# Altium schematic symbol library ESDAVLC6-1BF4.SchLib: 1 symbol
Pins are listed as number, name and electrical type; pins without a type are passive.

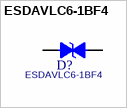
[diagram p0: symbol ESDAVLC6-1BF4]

## ESDAVLC6-1BF4
designator D?
footprint ST_0201B
pins: 1, 2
